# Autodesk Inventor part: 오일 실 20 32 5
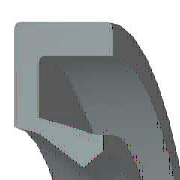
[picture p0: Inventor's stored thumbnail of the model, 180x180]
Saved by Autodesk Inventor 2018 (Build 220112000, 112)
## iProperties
IsCustomPart: 0
Created: 2012-02
Part Number: 오일 실 20 32 5
Material: 고무
Description: 오일 실 - 비스프링, 조립 GA
Document SubType Name: Modeling
Standard: JIS B 2402
Designer: mduedu
Standards Organization: JIS
Language: ko-KR
Size Designation: 20 32 5 A
Categories: <MemberInstance><Categories><Category DisplayName="샤프트 부품" InternalName="7f7aeb1f-a693-4053-b835-cee3144e0d98" Mnemonic="SHFT"><Category DisplayName="실링" Intern
Density: 0.93 g/cm^3
Appearance: Rubber-Black
Author: mduedu
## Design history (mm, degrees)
fillet "모깎기2" dims "d33" = 0.5
body "Solid1"
revolve "회전1" stored, may be unused: angle "d27" = 360 deg
fillet "모깎기1" dims "d28" = 0.25 (= 0.05 x b)
sketch "스케치2"
  geometry: L1 (11.971, -3.75)-(12.571, -5); L2 (11.171, -3.438)-(11.971, -3.75); L3 (10, -1.375)-(11.171, -3.438); L4 (10.923, -0.75)-(10, -1.375); L5 (13.6, -4.375)-(10.923, -0.75); L6 (13.6, -0.25)-(13.6, -4.375); L7 (14.8, -0.25)-(13.6, -0.25); L8 (14.8, 0)-(14.8, -0.25); L9 (16, 0)-(14.8, 0); L10 (16, -5)-(16, 0); L11 (12.571, -5)-(16, -5); L12 (0, -9.6)-(0, 1.6) reference; L13 (28, 0)-(14, 0) reference
  constraints: 22 end point, 3 horizontal, 3 vertical
  dimensions: "d2" = 5 distance of L10.start L9.start (= b); "d4" = 1.2 distance of L9.start L8.start (= 0.1 x dd - 0.1 x Diam); "d6" = 0.25 distance of L8.start L7.start (= 0.05 x b); "d8" = 0.92308 horizontal distance of L4.start L3.start (= 0.0769231 x dd - 0.0769231 x Diam); "d10" = 0.625 vertical distance of L5.start L10.start (= 0.125 x b); "d12" = 1.2 distance of L7.start L6.start (= 0.1 x dd - 0.1 x Diam); "d14" = 0.5 vertical distance of L4.start L6.start (= 0.1 x b); "d16" = 3.42857 distance of L1.end L10.start (= 0.285714 x dd - 0.285714 x Diam); "d18" = 0.6 horizontal distance of L1.start L1.end (= 0.05 x dd - 0.05 x Diam); "d20" = 0.625 vertical distance of L4.start L3.start (= 0.125 x b); "d22" = 1.25 vertical distance of L1.start L1.end (= 0.25 x b); "d24" = 0.8 horizontal distance of L2.start L1.start (= 0.0666667 x dd - 0.0666667 x Diam); "d26" = 0.3125 vertical distance of L2.start L1.start (= 0.0625 x b); "d29" = 0 distance between parallel lines of L13 L9; "d30" = 10 distance from line of L3.start L12 (= 0.5 x Diam); "d31" = 16 distance between parallel lines of L12 L10 (= 0.5 x dd)
other parameters: "dd" = 32 [user parameter; used in 7 equation terms], "b" = 5 [user parameter; used in 8 equation terms], "d1" = 8 (derived), "d3" = 2 (derived), "d5" = 0.4 (derived), "d7" = 1.53846 (derived), "d9" = 1 (derived), "d11" = 2 (derived), "d13" = 0.8 (derived), "d15" = 5.71429 (derived), "d17" = 1 (derived), "d19" = 1 (derived), "d21" = 2 (derived), "d23" = 1.33333 (derived), "d25" = 0.5 (derived), "d32" = 0
